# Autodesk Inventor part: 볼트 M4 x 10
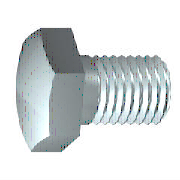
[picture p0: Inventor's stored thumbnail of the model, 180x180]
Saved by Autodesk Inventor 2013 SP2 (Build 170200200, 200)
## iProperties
Created: 2012-02
Part Number: 볼트 M4 x 10
Material: 스테인리스강
Description: 6각 머리 나사
Document SubType Name: Modeling
Standard: ISO 4017
Designer: mduedu
Standard Revision: Third edition 1999-08-15
Standards Organization: ISO
Language: ko-KR
Size Designation: M4 x 10
Categories: <MemberInstance><Categories><Category DisplayName="조임쇠" InternalName="e4da775c-781d-43d5-af7c-5136215cf5a6" Mnemonic="FSTN"><Category DisplayName="볼트" InternalN
Density: 8.08 g/cm^3
IsCustomPart: 0
Author: mduedu
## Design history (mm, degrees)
sketch "스케치1"
  geometry: L1 (0, 3.015)-(0, 2); L2 (2.1, 2)-(10, 2); L3 (10, 2)-(10, 0); L4 (10, 0)-(-0.4, 0); L5 (-2.48, 0)-(12.08, 0) reference; L6 (-0.4, 0)-(-0.4, 3.015); L7 (-0.4, 3.015)-(0, 3.015); L8 (2.1, 2)-(1.67, 2); L9 (1.67, 2)-(0, 2); L10 (0, -0.603)-(0, 3.618) reference
  constraints: 16 end point, 2 collinear, 2 perpendicular, 1 parallel
  dimensions: "d0" = 10 distance between parallel lines of L3 L1 (= NLG); "d1" = 7.9 distance from line of L2.start L3 (= GEL); "d2" = 4 diameter of L2 L4 (= GD); "d9" = 0.4001 distance between parallel lines of L6 L1 (computed from SD); "d10" = 6.03 diameter of L7 L4 (= SD2); "d13" = 0.42952 distance of L2.start L8.end (computed from GAL); "d14" = 4 diameter of L9 L4 (= BDM)
revolve "본체" sketch "스케치1" stored, may be unused: angle "d12" = 90 deg
sketch "스케치2"
  geometry: L1 (0, 4.041)-(3.5, 2.021); L2 (3.5, 2.021)-(3.5, -2.021); L3 (3.5, -2.021)-(0, -4.041); L4 (0, -4.041)-(-3.5, -2.021); L5 (-3.5, -2.021)-(-3.5, 2.021); L6 (-3.5, 2.021)-(0, 4.041); 2 further points
  constraints: 12 end point, 1 coincident, 1 vertical, 11 other
  dimensions: "d11" = 7 distance between parallel lines of L5 L2 (= SW)
extrude "머리" join sketch "스케치2" distance "d3" = 2.4 (= KOH - SD); taper "d4" = 0 deg
sketch "스케치4"
  geometry: L1 (-2.8, 3.5)-(-2.8, 4.041); L2 (-2.8, 4.041)-(-2.487, 4.041); L3 (-2.487, 4.041)-(-2.8, 3.5); L4 (-3.28, 0)-(0.08, 0) reference; L5 (-0.4, 4.041)-(-2.8, 4.041) reference; L6 (-2.8, 2.021)-(-2.8, 4.041) reference
  constraints: 6 end point, 2 collinear, 1 perpendicular, 1 vertical
  dimensions: "d5" = 30 deg angle of L3 L1 (= ANG1); "d19" = 7 diameter of L1.start L4 (= SW0)
revolve "모따기1" sketch "스케치4" stored, may be unused: angle "d21" = 90 deg
workplane "Work Plane1"
body "Solid1"
feature "스레드" dims "d15" = 7.9 (= GEL), "d16" = 0
chamfer "모따기2" distance "d6" = 0.42941 (= -0.5 x SPD + 0.5 x GD); stored, may be unused: second distance "d7" = 0.42952 (computed from GUL), angle "d55" = 45 deg
other parameters: "NLG" = 10 [user parameter; used in 1 equation term], "GD" = 4 (= NND) [user parameter; used in 2 equation terms], "BDM" = 4 (= NND) [user parameter; used in 1 equation term], "KOH" = 2.8 [user parameter; used in 1 equation term], "GEL" = 7.9 [user parameter; used in 2 equation terms], "SW" = 7 [user parameter; used in 2 equation terms], "SW0" = 7 (= SW) [user parameter; used in 1 equation term], "SPD" = 3.14117 (= NND - 1.2269 x PTC) [user parameter; used in 1 equation term], "SD2" = 6.03 [user parameter; used in 2 equation terms], "SD" = 0.4 [user parameter; used in 2 equation terms], "ANG1" = 30 deg [user parameter; used in 1 equation term], "GAL" = 0.42941 (= 0.61345 x PTC) [user parameter; used in 1 equation term], "GUL" = 0.42941 (= 0.61345 x PTC) [user parameter; used in 1 equation term], "d8" = 0, "RR" = 0.2 [user parameter], "d57" = 0, "d58" = 0, "TPU" = 14.28571 (computed from PTC) [user parameter], "GD1" = 3.14117 (= THREADDIA - 1.2269 x PTC) [user parameter], "THREADDIA" = 4 [user parameter; used in 1 equation term], "SDH" = 6.03 (= SD2) [user parameter], "SDHG" = 2.1 [user parameter], "TOA" = 30 deg [user parameter], "PTC" = 0.7 [user parameter; used in 5 equation terms], "NND" = 4 [user parameter; used in 3 equation terms], "E0" = 8.085 [user parameter]
